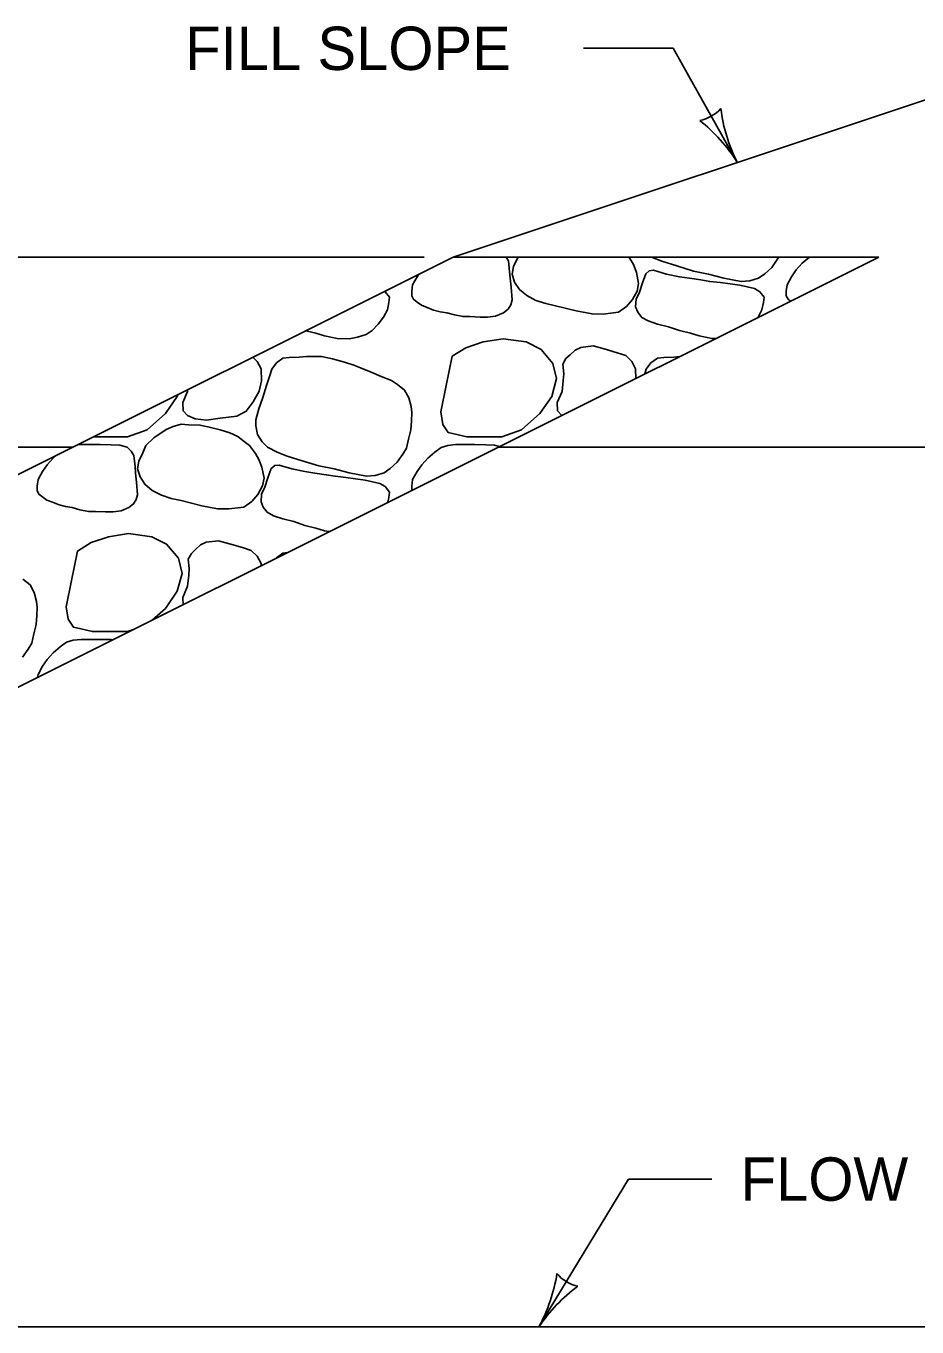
# Model space of a CAD drawing. Extents: x 49991.4 to 50021, y 49987.6 to 50011.4.
# Drawn here: x 50004.068 to 50005.301, y 50004.739 to 50006.54 of the extents above; entities that cross this region are included whole.
import ezdxf

# ---------------------------------------------------------------- set-up
doc = ezdxf.new("R2010")
doc.units = 0
for name, color, linetype in [('Default', 7, 'Continuous'), ('Level 1', 7, 'Continuous'), ('Level 2', 7, 'Continuous'), ('Level 3', 7, 'Continuous')]:
    doc.layers.add(name, color=color, linetype=linetype)

msp = doc.modelspace()

# ---------------------------------------------------------------- linework, layer by layer
at = {"layer": 'Default'}
for points in [[(50004.6116, 50006.1965), (50004.6093, 50006.1931), (50004.6031, 50006.1819), (50004.6019, 50006.173), (50004.6019, 50006.1666), (50004.6044, 50006.1618), (50004.6097, 50006.1577), (50004.6154, 50006.1536), (50004.6232, 50006.1506), (50004.6323, 50006.1468), (50004.6413, 50006.1446), (50004.6503, 50006.1431), (50004.661, 50006.1401), (50004.6729, 50006.1379), (50004.6827, 50006.1379), (50004.6967, 50006.1371), (50004.7069, 50006.1371), (50004.718, 50006.1386), (50004.7287, 50006.1431), (50004.7353, 50006.1483), (50004.739, 50006.1543), (50004.741, 50006.161), (50004.7394, 50006.1786), (50004.7381, 50006.1909), (50004.7373, 50006.1998), (50004.7357, 50006.2151), (50004.7327, 50006.2203)], [(50004.749, 50006.2203), (50004.7484, 50006.2189), (50004.7426, 50006.2073), (50004.741, 50006.1968), (50004.7443, 50006.1857), (50004.7509, 50006.1756), (50004.7611, 50006.167), (50004.7738, 50006.1603), (50004.7874, 50006.1558), (50004.8009, 50006.1528), (50004.8296, 50006.1457), (50004.8514, 50006.1416), (50004.867, 50006.1412), (50004.8879, 50006.1439), (50004.899, 50006.1517), (50004.9072, 50006.1614), (50004.9138, 50006.1733), (50004.9158, 50006.1838), (50004.9129, 50006.1991), (50004.9088, 50006.2099), (50004.9039, 50006.2181), (50004.9023, 50006.2203)], [(50005.1098, 50006.2203), (50005.1078, 50006.217), (50005.1, 50006.2058), (50005.0906, 50006.1972), (50005.082, 50006.1912), (50005.0697, 50006.1875), (50005.0578, 50006.1864), (50005.0336, 50006.1912), (50005.0126, 50006.1968), (50004.9917, 50006.2009), (50004.9687, 50006.208), (50004.9478, 50006.2144), (50004.9338, 50006.22), (50004.9332, 50006.2203)], [(50005.1526, 50006.2203), (50005.1522, 50006.22), (50005.1423, 50006.2118), (50005.1341, 50006.2024), (50005.1275, 50006.1931), (50005.1214, 50006.1819), (50005.1201, 50006.173), (50005.1201, 50006.1666), (50005.1226, 50006.1618), (50005.1259, 50006.1592)], [(50005.0226, 50006.1075), (50005.0172, 50006.1077), (50004.9995, 50006.111), (50004.9876, 50006.1147), (50004.9724, 50006.1185), (50004.9573, 50006.1237), (50004.9421, 50006.1274), (50004.9289, 50006.1319), (50004.9203, 50006.1368), (50004.9146, 50006.1439), (50004.9117, 50006.1513), (50004.9125, 50006.1618), (50004.917, 50006.1715), (50004.9212, 50006.1845), (50004.9257, 50006.1972), (50004.9306, 50006.2013), (50004.9367, 50006.2021), (50004.9544, 50006.1968), (50004.9724, 50006.1931), (50004.9864, 50006.1909), (50005.002, 50006.1886), (50005.0143, 50006.1864), (50005.0291, 50006.1849), (50005.0558, 50006.1812), (50005.0763, 50006.1767), (50005.0837, 50006.1722), (50005.0894, 50006.1648), (50005.0886, 50006.1573), (50005.0865, 50006.1472), (50005.0812, 50006.1371), (50005.0808, 50006.1367)], [(50004.5644, 50006.1728), (50004.5654, 50006.1722), (50004.5711, 50006.1648), (50004.5703, 50006.1573), (50004.5683, 50006.1472), (50004.5629, 50006.1371), (50004.5556, 50006.1274), (50004.5473, 50006.1185), (50004.5391, 50006.1133), (50004.5268, 50006.1095), (50004.5153, 50006.1073), (50004.4989, 50006.1077), (50004.4813, 50006.111), (50004.4694, 50006.1147), (50004.4552, 50006.1182)], [(50004.912, 50006.0523), (50004.9117, 50006.0655), (50004.9064, 50006.0759), (50004.8982, 50006.0838), (50004.8863, 50006.0879), (50004.8682, 50006.0931), (50004.853, 50006.0972), (50004.8358, 50006.0953), (50004.828, 50006.0916), (50004.821, 50006.0849), (50004.8153, 50006.0797), (50004.8108, 50006.0718), (50004.8124, 50006.0588), (50004.8116, 50006.0494), (50004.8099, 50006.0341), (50004.8034, 50006.0188), (50004.8038, 50006.0073), (50004.8097, 50006.0011)], [(50004.2919, 50006.0366), (50004.2917, 50006.0341), (50004.2851, 50006.0188), (50004.2855, 50006.0073), (50004.2917, 50006.0009), (50004.3024, 50005.9965), (50004.3179, 50005.9946), (50004.3368, 50005.9972), (50004.3598, 50006.0002), (50004.3729, 50006.0069), (50004.3824, 50006.02), (50004.391, 50006.0345), (50004.3939, 50006.0491), (50004.3935, 50006.0655), (50004.3881, 50006.0759), (50004.3821, 50006.0817)], [(50004.9246, 50006.0586), (50004.9265, 50006.0652), (50004.933, 50006.0738), (50004.942, 50006.0801), (50004.9507, 50006.0812), (50004.9646, 50006.0816), (50004.9725, 50006.0825)], [(50004.1616, 50005.9714), (50004.2086, 50005.9714), (50004.2357, 50005.9812), (50004.2611, 50006.0035), (50004.2775, 50006.0274), (50004.2781, 50006.0297)], [(50004.1102, 50005.9458), (50004.1058, 50005.942), (50004.0976, 50005.9327), (50004.091, 50005.9234), (50004.0849, 50005.9122), (50004.0836, 50005.9032), (50004.0836, 50005.8969), (50004.0861, 50005.892), (50004.0914, 50005.8879), (50004.0972, 50005.8838), (50004.105, 50005.8808), (50004.114, 50005.8771), (50004.123, 50005.8749), (50004.1321, 50005.8734), (50004.1427, 50005.8704), (50004.1546, 50005.8682), (50004.1645, 50005.8682), (50004.1784, 50005.8674), (50004.1887, 50005.8674), (50004.1998, 50005.8689), (50004.2104, 50005.8734), (50004.217, 50005.8786), (50004.2207, 50005.8846), (50004.2227, 50005.8913), (50004.2211, 50005.9088), (50004.2199, 50005.9211), (50004.2191, 50005.9301), (50004.2174, 50005.9454), (50004.2137, 50005.9517), (50004.208, 50005.9573), (50004.1981, 50005.96), (50004.1862, 50005.9603), (50004.171, 50005.9607), (50004.1559, 50005.9607), (50004.1444, 50005.9607), (50004.139, 50005.9601)], [(50004.7236, 50005.958), (50004.7164, 50005.96), (50004.7045, 50005.9603), (50004.6893, 50005.9607), (50004.6741, 50005.9607), (50004.6626, 50005.9607), (50004.652, 50005.9596), (50004.6425, 50005.9566), (50004.6339, 50005.9503), (50004.624, 50005.942), (50004.6158, 50005.9327), (50004.6093, 50005.9234), (50004.6031, 50005.9122), (50004.6019, 50005.9032), (50004.6019, 50005.8972)], [(50004.4877, 50005.8401), (50004.4813, 50005.8413), (50004.4694, 50005.845), (50004.4542, 50005.8488), (50004.439, 50005.854), (50004.4238, 50005.8577), (50004.4107, 50005.8622), (50004.4021, 50005.867), (50004.3963, 50005.8741), (50004.3935, 50005.8816), (50004.3943, 50005.892), (50004.3988, 50005.9017), (50004.4029, 50005.9148), (50004.4074, 50005.9275), (50004.4123, 50005.9316), (50004.4185, 50005.9323), (50004.4361, 50005.9271), (50004.4542, 50005.9234), (50004.4681, 50005.9211), (50004.4837, 50005.9189), (50004.496, 50005.9167), (50004.5108, 50005.9152), (50004.5375, 50005.9114), (50004.558, 50005.907), (50004.5654, 50005.9025), (50004.5711, 50005.895), (50004.5703, 50005.8876), (50004.5689, 50005.8807)], [(50004.2427, 50005.7176), (50004.2611, 50005.7338), (50004.2775, 50005.7577), (50004.2841, 50005.7823), (50004.2792, 50005.8032), (50004.2627, 50005.8226), (50004.2422, 50005.8331), (50004.2102, 50005.8376), (50004.1823, 50005.8331), (50004.1585, 50005.8249), (50004.1395, 50005.8133), (50004.1314, 50005.7726), (50004.124, 50005.7361), (50004.1265, 50005.7189), (50004.1339, 50005.7077), (50004.1602, 50005.7017), (50004.2086, 50005.7017), (50004.2169, 50005.7047)], [(50004.3935, 50005.793), (50004.3935, 50005.7958), (50004.3881, 50005.8062), (50004.3799, 50005.814), (50004.368, 50005.8182), (50004.35, 50005.8234), (50004.3348, 50005.8275), (50004.3175, 50005.8256), (50004.3097, 50005.8219), (50004.3028, 50005.8152), (50004.297, 50005.8099), (50004.2925, 50005.8021), (50004.2941, 50005.789), (50004.2933, 50005.7797), (50004.2917, 50005.7644), (50004.2851, 50005.7491), (50004.2855, 50005.739)], [(50004.4143, 50005.8034), (50004.4148, 50005.804), (50004.4238, 50005.8104), (50004.4299, 50005.8112)], [(50004.0639, 50005.7742), (50004.0738, 50005.7663), (50004.0795, 50005.7559), (50004.0828, 50005.7436), (50004.0836, 50005.7354), (50004.0832, 50005.7234), (50004.0824, 50005.7115), (50004.0791, 50005.6984), (50004.0762, 50005.6857), (50004.0713, 50005.6775), (50004.0635, 50005.6663)], [(50004.1886, 50005.6905), (50004.1862, 50005.6906), (50004.171, 50005.691), (50004.1559, 50005.691), (50004.1444, 50005.691), (50004.1337, 50005.6899), (50004.1243, 50005.6869), (50004.1156, 50005.6805), (50004.1058, 50005.6723), (50004.0976, 50005.663), (50004.091, 50005.6537), (50004.0849, 50005.6425), (50004.0843, 50005.6384)]]:
    msp.add_lwpolyline(points, dxfattribs=at)
for points in [[(50004.6578, 50006.083), (50004.6497, 50006.0424), (50004.6423, 50006.0058), (50004.6448, 50005.9886), (50004.6522, 50005.9774), (50004.6784, 50005.9714), (50004.7268, 50005.9714), (50004.7539, 50005.9812), (50004.7794, 50006.0035), (50004.7958, 50006.0274), (50004.8023, 50006.0521), (50004.7974, 50006.073), (50004.781, 50006.0924), (50004.7605, 50006.1028), (50004.7285, 50006.1073), (50004.7006, 50006.1028), (50004.6768, 50006.0946)], [(50004.4324, 50006.0812), (50004.4464, 50006.0816), (50004.4562, 50006.0827), (50004.4771, 50006.0824), (50004.4923, 50006.0794), (50004.5087, 50006.0749), (50004.5219, 50006.0704), (50004.5309, 50006.0667), (50004.5457, 50006.0607), (50004.5596, 50006.0547), (50004.574, 50006.0495), (50004.5822, 50006.0439), (50004.592, 50006.0361), (50004.5978, 50006.0256), (50004.6011, 50006.0133), (50004.6019, 50006.0051), (50004.6015, 50005.9932), (50004.6007, 50005.9812), (50004.5974, 50005.9682), (50004.5945, 50005.9555), (50004.5896, 50005.9473), (50004.5818, 50005.9361), (50004.5723, 50005.9275), (50004.5637, 50005.9215), (50004.5514, 50005.9178), (50004.5395, 50005.9167), (50004.5153, 50005.9215), (50004.4944, 50005.9271), (50004.4734, 50005.9312), (50004.4505, 50005.9383), (50004.4295, 50005.9446), (50004.4156, 50005.9502), (50004.4025, 50005.9573), (50004.3951, 50005.9644), (50004.3885, 50005.9745), (50004.3864, 50005.9868), (50004.3864, 50005.9947), (50004.3906, 50006.01), (50004.3959, 50006.026), (50004.4008, 50006.0424), (50004.4057, 50006.0562), (50004.4082, 50006.0652), (50004.4148, 50006.0738), (50004.4238, 50006.0801)], [(50004.2621, 50005.9816), (50004.2449, 50005.97), (50004.2342, 50005.9592), (50004.2301, 50005.9491), (50004.2244, 50005.9376), (50004.2227, 50005.9271), (50004.226, 50005.9159), (50004.2326, 50005.9058), (50004.2429, 50005.8973), (50004.2556, 50005.8905), (50004.2691, 50005.8861), (50004.2827, 50005.8831), (50004.3114, 50005.876), (50004.3331, 50005.8719), (50004.3487, 50005.8715), (50004.3697, 50005.8741), (50004.3807, 50005.882), (50004.3889, 50005.8917), (50004.3955, 50005.9036), (50004.3976, 50005.9141), (50004.3947, 50005.9294), (50004.3906, 50005.9402), (50004.3857, 50005.9484), (50004.3775, 50005.9596), (50004.3684, 50005.9663), (50004.3614, 50005.9719), (50004.3504, 50005.9768), (50004.3368, 50005.9812), (50004.32, 50005.9853), (50004.3089, 50005.9876), (50004.2929, 50005.9879), (50004.2831, 50005.9887), (50004.272, 50005.9857)]]:
    msp.add_lwpolyline(points, close=True, dxfattribs=at)
at = {"layer": 'Level 1'}
for p, q in [((50004.6593, 50006.2203), (50005.3807, 50006.4608)), ((50002.2234, 50005.0023), (50004.6593, 50006.2203)), ((50002.3102, 50004.7514), (50005.2481, 50006.2203)), ((50004.6593, 50006.2203), (50005.2481, 50006.2203)), ((50003.4749, 50005.957), (50004.1327, 50005.957)), ((50004.7215, 50005.957), (50007.2456, 50005.957)), ((50002.3102, 50004.7389), (50007.2456, 50004.7389))]:
    msp.add_line(p, q, dxfattribs=at)
at = {"layer": 'Level 3'}
for p, q in [((50004.9636, 50006.5093), (50004.8398, 50006.5093)), ((50005.0524, 50006.3513), (50004.9636, 50006.5093)), ((50004.6193, 50006.2203), (50001.628, 50006.2203)), ((50004.7779, 50004.7389), (50004.9017, 50004.9437)), ((50004.9017, 50004.9437), (50005.0171, 50004.9437))]:
    msp.add_line(p, q, dxfattribs=at)
for centre, radius, start, end in [((50004.9896, 50006.4631), 0.0548, 281.4899, 317.2123), ((50005.2505, 50006.4522), 0.2223, 186.8071, 206.9906), ((50004.8552, 50006.2273), 0.233, 32.1784, 51.4283), ((50004.5728, 50004.8495), 0.233, 331.6747, 350.9245), ((50004.8442, 50004.8486), 0.0548, 220.9862, 256.7085), ((50004.9633, 50004.6161), 0.2223, 126.3034, 146.4869)]:
    msp.add_arc(centre, radius, start, end, dxfattribs=at)

# ---------------------------------------------------------------- texts
at = {"layer": 'Level 2'}
for s, p in [('FILL SLOPE', (50004.2886, 50006.4793)), ('FLOW LINE', (50005.0571, 50004.9137))]:
    msp.add_text(s, height=0.06, dxfattribs=at).set_placement(p)

doc.saveas('drawing.dxf')
